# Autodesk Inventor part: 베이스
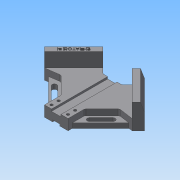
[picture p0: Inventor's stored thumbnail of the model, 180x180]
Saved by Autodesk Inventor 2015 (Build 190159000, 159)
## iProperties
Created: 2020-05
Part Number: 베이스
Material: 알루미늄 6061
Document SubType Name: Modeling
Designer: LINEART-SSD.D4.16.06
Density: 2.7 g/cm^3
Appearance: 기본값
Mass: 571.622 g
Surface Area: 407.173 cm^2
Volume: 211.712 cm^3
Author: LINEART-SSD.D4.16.06
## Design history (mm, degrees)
sketch "스케치1"
  geometry: L1 (0, 84.853)-(84.853, 0); L2 (84.853, 0)-(0, -84.853); L3 (0, -84.853)-(-84.853, 0); L4 (-84.853, 0)-(0, 84.853); L5 (0, 84.853)-(0, -84.853); L6 (84.853, 0)-(-84.853, 0); L7 (0, 84.853)-(120, 84.853); 1 further point
  constraints: 14 end point, 2 midpoint, 2 parallel, 1 equal length, 1 horizontal, 1 perpendicular
  dimensions: "d0" = 120 distance of L1.start L1.end; "d1" = 45 deg angle of L1 L7; "d2" = 120 distance of L1.end L2.end
extrude "돌출1" new body sketch "스케치1" stored distance "d3" = 42; taper "d4" = 0 deg
sketch "스케치2"
  geometry: L1 (-20, -84.853)-(20, -84.853); L2 (20, -84.853)-(20, -64.853); L3 (20, -64.853)-(-20, -64.853); L4 (-20, -64.853)-(-20, -84.853); L5 (0, -84.853)-(84.853, 0) reference; L6 (-84.853, 0)-(0, -84.853) reference; 1 further point
  constraints: 8 end point, 2 parallel, 2 point on line, 1 horizontal, 1 midpoint, 1 perpendicular
  dimensions: "d5" = 20 distance of L1.end L2.end
extrude "돌출2" cut sketch "스케치2" stored distance "d6" = 42; taper "d7" = 0 deg
sketch "스케치3"
  geometry: L1 (-35.355, 49.497)-(-24.749, 38.891); L2 (-16.005, 30.147)-(0, 30.147); L3 (0, 30.147)-(0, 84.853); L4 (0, 84.853)-(-35.355, 49.497); L5 (0, 84.853)-(-84.853, 0) reference; L6 (-20, -64.853)-(20, -64.853) reference; L7 (-24.749, 38.891)-(-74.246, -10.607); L8 (-74.246, -10.607)-(-20, -64.853); L9 (-20, -64.853)-(0, -64.853); L10 (0, -64.853)-(0, 30.147); L11 (-84.853, 0)-(-20, -64.853) reference; L12 (-24.749, 38.891)-(-16.005, 30.147); L13 (84.853, 0)-(0, 84.853) reference; L14 (20, -64.853)-(0, -64.853); L15 (74.246, -10.607)-(20, -64.853); L16 (24.749, 38.891)-(74.246, -10.607); L17 (16.005, 30.147)-(0, 30.147); L18 (24.749, 38.891)-(16.005, 30.147); L19 (35.355, 49.497)-(24.749, 38.891); L20 (0, 84.853)-(35.355, 49.497); 1 further point
  constraints: 32 end point, 5 perpendicular, 5 symmetric about line, 2 collinear, 2 horizontal, 1 midpoint
  dimensions: "d8" = 95 distance between parallel lines of L6 L2; "d9" = 15 distance between parallel lines of L5 L7; "d10" = 50 distance between parallel lines of L13 L1
extrude "돌출3" cut sketch "스케치3" distance "d11" = 24; taper "d12" = 0 deg
extrude "돌출4" cut sketch "스케치3" stored distance "d13" = 24; taper "d14" = 0 deg
sketch "스케치4"
  geometry: L1 (-74.246, -10.607)-(-68.059, -9.723); L2 (-49.497, -7.071)-(-20, -36.569); L3 (-20, -36.569)-(-20, -57.782); L4 (-20, -64.853)-(-74.246, -10.607); L5 (-68.059, -9.723)-(-20, -57.782); L6 (-20, -57.782)-(-20, -64.853); L7 (-68.059, -9.723)-(-49.497, -7.071); L8 (-20, -64.853)-(-74.246, -10.607) reference; L9 (-35.355, 49.497)-(-84.853, 0) reference; L10 (-84.853, 0)-(-74.246, -10.607) reference; 1 further point
  constraints: 14 end point, 2 collinear, 2 parallel, 2 vertical
  dimensions: "d15" = 30 distance from line of L2.start L9; "d16" = 5 distance between parallel lines of L5 L4; "d17" = 20 distance from line of point (0, 0) L6; "d18" = 20 distance between parallel lines of L10 L2
extrude "돌출5" cut sketch "스케치4" stored distance "d19" = 24; taper "d20" = 0 deg
extrude "돌출6" cut sketch "스케치4" distance "d21" = 10; taper "d22" = 0 deg
sketch "스케치5"
  geometry: L1 (-49.497, -18.385)-(-29.698, -38.184); L2 (-52.326, -21.213)-(-32.527, -41.012); L3 (-26.87, -35.355)-(-46.669, -15.556); L4 (-20, -57.782)-(-68.059, -9.723) reference; L5 (-84.853, 0)-(-74.246, -10.607) reference; L6 (-35.355, 49.497)-(-84.853, 0) reference; A1 r 4 centre (-49.497, -18.385) between (-46.669, -15.556) and (-52.326, -21.213); A2 r 4 centre (-29.698, -38.184) between (-32.527, -41.012) and (-26.87, -35.355); 2 further points
  constraints: 8 end point, 4 point on circle, 4 tangent, 2 centre point, 2 parallel, 1 midpoint
  dimensions: "d23" = 12 distance between parallel lines of L1 L5; "d24" = 28 distance of L1.start L1.end; "d25" = 38 distance from line of L6 L1.start; "d26" = 8 distance between parallel lines of L3 L2
extrude "돌출7" cut sketch "스케치5" stored distance "d27" = 10; taper "d28" = 0 deg
fillet "모깎기1" dims "d29" = 5
sketch "스케치7"
  geometry: L1 (20, 64.853)-(-20, 64.853) reference; 3 further points
  constraints: 1 vertical alignment
  dimensions: "d33" = 12 distance of point (-14, 46.853) point (-14, 58.853); "d34" = 6 distance from line of L1 point (-14, 58.853); "d35" = 14 horizontal distance of point (0, 0) point (-14, 58.853)
hole "구멍1" sketch "스케치7" diameter "d36" = 4.5; stored, may be unused: countersink angle "d40" = 90 deg, drill point angle "d42" = 118 deg; dims "d37" = 6, "d38" = 8, "d39" = 10, "d41" = 8
sketch "스케치8"
  geometry: L1 (40, 18)-(0, 18) reference; L2 (40, 0)-(0, 0) reference; L3 (12, 18)-(28, 18); L4 (28, 18)-(28, 14.5); L5 (28, 14.5)-(12, 14.5); L6 (12, 14.5)-(12, 18); L7 (14, 3)-(26, 3); L8 (26, 3)-(26, 0); L9 (26, 0)-(14, 0); L10 (14, 0)-(14, 3); 3 further points
  constraints: 16 end point, 4 midpoint, 4 parallel, 2 horizontal, 2 perpendicular
  dimensions: "d43" = 16 distance between parallel lines of L4 L6; "d44" = 3.5 distance of L3.end L4.end; "d45" = 12 distance between parallel lines of L8 L10; "d46" = 3 distance of L7.end L8.end
extrude "돌출8" cut sketch "스케치8" stored distance "d47" = 10; taper "d48" = 0 deg
chamfer "모따기1" distance "d49" = 5; stored, may be unused: second distance "d50" = 15, angle "d51" = 45 deg
chamfer "모따기2" distance "d52" = 5; stored, may be unused: second distance "d53" = 15, angle "d54" = 45 deg
sketch "스케치9"
  geometry: L1 (-74.246, -10.607)-(-24.749, 38.891) reference; L2 (-24.749, 38.891)-(-31.82, 45.962) reference; L3 (-35.355, 49.497)-(-84.853, 0) reference; 2 further points
  constraints: 1 other
  dimensions: "d55" = 35 distance from line of L2 point (-53.033, 17.678); "d57" = 5 distance from line of L1 point (-53.033, 17.678)
feature "엠보싱1" sketch "스케치9" dims "d0" = 120, "d1" = 45 deg, "d2" = 120, "d8" = 95, "d9" = 15, "d10" = 50, "d58" = 0.5, "d59" = 0
fillet "모깎기2" dims "d60" = 5
node "솔리드1"
pattern_linear "직사각형 패턴1" dims "d63" = 28, "d66" = 12
mirror "대칭1"
